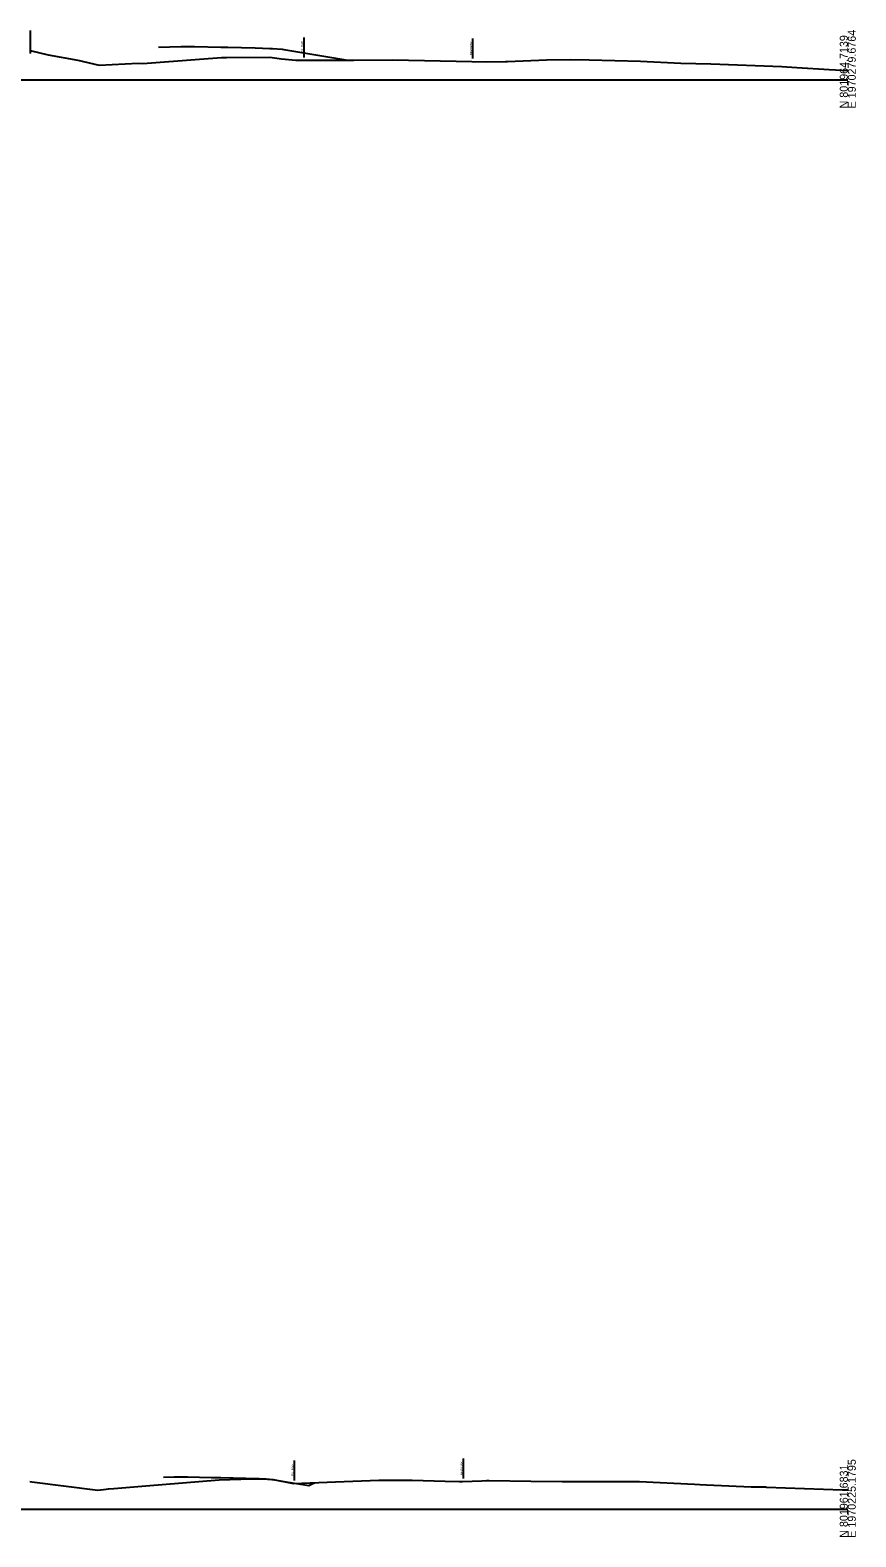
# Model space of a CAD drawing. Extents: x -4026 to 9638, y -10 to 19609.
# Drawn here: x 6414 to 6703, y -10 to 517 of the extents above; entities that cross this region are included whole.
import ezdxf

# ---------------------------------------------------------------- set-up
doc = ezdxf.new("R2010")
doc.units = 0
for name, color, linetype in [('RD_EX_Road', 7, 'Continuous'), ('RD_GPK_XS_Cell', 7, 'Continuous'), ('RD_XS_ExGround', 7, 'Continuous'), ('RD_XS_ExPaveRet', 7, 'Continuous'), ('RD_XS_ExRW', 7, 'Continuous'), ('RD_XS_NewRW', 7, 'Continuous'), ('RD_XS_Pave', 7, 'Continuous')]:
    doc.layers.add(name, color=color, linetype=linetype)

msp = doc.modelspace()

# ---------------------------------------------------------------- linework, layer by layer
at = {"layer": 'RD_EX_Road'}
msp.add_line((6413.74, 517.25), (6413.74, 510.25), dxfattribs=at)
at = {"layer": 'RD_GPK_XS_Cell'}
for p, q in [((6350, 500), (6700, 500)), ((6350, 0), (6700, 0))]:
    msp.add_line(p, q, dxfattribs=at)
at = {"layer": 'RD_XS_ExGround'}
for points in [[(6413.74, 510.25), (6420.01, 508.78), (6430.43, 506.89), (6437.9, 505.11), (6451.54, 505.77), (6453.23, 505.74), (6473.04, 507.23), (6480.7, 507.8), (6482.49, 507.85), (6497.65, 507.92), (6501.75, 507.32), (6506.75, 506.84), (6527.05, 506.85), (6540.76, 506.99), (6568.39, 506.44), (6573.44, 506.29), (6580.18, 506.43), (6580.85, 506.45), (6594.57, 506.94), (6602.83, 507.16), (6609.44, 507.03), (6627.4, 506.57), (6641.55, 505.87), (6652.03, 505.57), (6676.88, 504.61), (6682.15, 504.28), (6693.48, 503.58), (6700, 503.3)], [(6413.67, 9.71), (6414.4, 9.61), (6437.4, 6.63), (6440.4, 6.95), (6441.2, 7.07), (6443.06, 7.23), (6454.27, 8.14), (6467.06, 9.23), (6479.97, 10.3), (6491.2, 10.55), (6496.33, 10.66), (6498.84, 10.32), (6505.99, 8.97), (6520.69, 9.54), (6535.81, 10.14), (6543.54, 10.18), (6547.48, 10.11), (6559.01, 9.81), (6563.91, 9.67), (6565.11, 9.71), (6571.84, 9.94), (6573.57, 9.99), (6574.46, 9.98), (6589.02, 9.78), (6600.06, 9.73), (6620.07, 9.72), (6627.03, 9.69), (6646.29, 8.72), (6648.16, 8.67), (6650.59, 8.54), (6666.16, 7.77), (6671.2, 7.76), (6671.57, 7.74), (6698.14, 6.78), (6700, 6.72)]]:
    msp.add_lwpolyline(points, dxfattribs=at)
at = {"layer": 'RD_XS_ExPaveRet'}
msp.add_line((6413.74, 510.25), (6413.74, 509.25), dxfattribs=at)
at = {"layer": 'RD_XS_ExRW'}
for p, q in [((6509.63, 507.84), (6509.63, 514.84)), ((6506.34, 9.98), (6506.34, 16.98))]:
    msp.add_line(p, q, dxfattribs=at)
at = {"layer": 'RD_XS_NewRW'}
for p, q in [((6568.77, 507.43), (6568.77, 514.43)), ((6565.43, 10.72), (6565.43, 17.72))]:
    msp.add_line(p, q, dxfattribs=at)
at = {"layer": 'RD_XS_Pave'}
for points in [[(6458.66, 511.47), (6466.61, 511.64), (6468.53, 511.68), (6471.32, 511.62), (6480.56, 511.43), (6482.96, 511.38), (6492.58, 511.18), (6497.65, 510.97), (6498.6, 510.93), (6502.02, 510.66), (6502.61, 510.61), (6504.69, 510.26), (6524.99, 506.87)], [(6460.41, 11.23), (6464.19, 11.32), (6465.27, 11.35), (6468.84, 11.27), (6477.29, 11.1), (6480.54, 11.03), (6489.31, 10.85), (6493.88, 10.67), (6495.32, 10.61), (6498.41, 10.36), (6499.33, 10.28), (6502, 9.84), (6511.35, 8.28), (6512.54, 8.87), (6513.31, 9.25)]]:
    msp.add_lwpolyline(points, dxfattribs=at)

# ---------------------------------------------------------------- texts
at = {"layer": 'RD_GPK_XS_Cell'}
for s, p in [('E 1970279.6764', (6702.8, 490)), ('N 801964.7139', (6700, 490)), ('E 1970225.1795', (6702.8, -10)), ('N 801961.6831', (6700, -10))]:
    msp.add_text(s, height=2.8, rotation=90, dxfattribs=at).set_placement(p)
at = {"layer": 'RD_XS_ExRW'}
for p in [(6509.38, 509.52), (6506.09, 11.66)]:
    msp.add_text('EX. R/W ', height=0.75, rotation=90, dxfattribs=at).set_placement(p)
at = {"layer": 'RD_XS_NewRW'}
for p in [(6568.52, 508.58), (6565.18, 11.87)]:
    msp.add_text('NEW R/W ', height=0.75, rotation=90, dxfattribs=at).set_placement(p)

doc.saveas('drawing.dxf')
